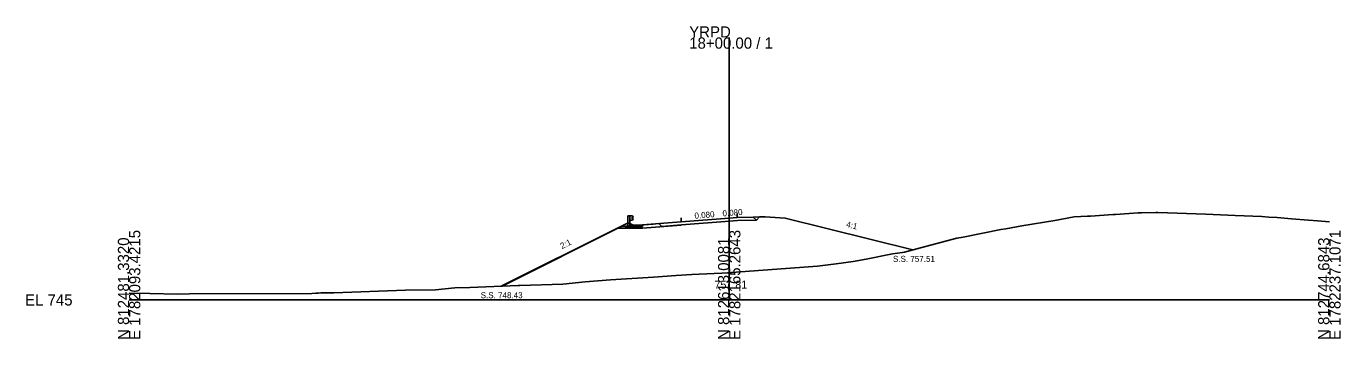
# Model space of a CAD drawing. Extents: x -26 to 1403, y -10 to 9544.
# Drawn here: x -25.7 to 302.8, y 7990.3 to 8068.4 of the extents above; entities that cross this region are included whole.
import ezdxf

# ---------------------------------------------------------------- set-up
doc = ezdxf.new("R2010")
doc.units = 0
for name, color, linetype in [('Exist Cross Section Cell', 7, 'Continuous'), ('Exist XS Center Line Elevation Label', 7, 'Continuous'), ('Exist XS Ground Line', 7, 'Continuous'), ('Prop XS Dump Level', 7, 'Continuous'), ('Prop XS Earthwork Shape', 7, 'Continuous'), ('Prop XS EOT Tick Mark', 7, 'Continuous'), ('Prop XS Finish Grade', 7, 'Continuous'), ('Prop XS Finish Grade CurbGutter', 7, 'Continuous'), ('Prop XS Finish Grade Earthwork', 7, 'Continuous'), ('Prop XS Finish Grade Paved Shoulder', 7, 'Continuous'), ('Prop XS Finish Grade Pavement', 7, 'Continuous'), ('Prop XS Guardrail', 7, 'Continuous'), ('Prop XS Pvmt Edge Slope', 7, 'Continuous'), ('Prop XS SE Text', 7, 'Continuous'), ('Prop XS Side Slope Text', 7, 'Continuous'), ('Prop XS SS Elevation Text', 7, 'Continuous'), ('Prop XS Subgrade CurbGutter', 7, 'Continuous'), ('Prop XS Subgrade Earthwork', 7, 'Continuous')]:
    doc.layers.add(name, color=color, linetype=linetype)

msp = doc.modelspace()

# ---------------------------------------------------------------- linework, layer by layer
at = {"layer": 'Exist Cross Section Cell'}
for p, q in [((150, 8000), (150, 8065.58)), ((0, 8000), (150, 8000)), ((150, 8000), (300, 8000))]:
    msp.add_line(p, q, dxfattribs=at)
at = {"layer": 'Exist XS Ground Line'}
for p, q in [((223.12, 8018.51), (231.37, 8019.86)), ((231.37, 8019.86), (236.24, 8020.8)), ((236.24, 8020.8), (239.53, 8020.93)), ((239.53, 8020.93), (240.32, 8020.96)), ((240.32, 8020.96), (245.93, 8021.33)), ((245.93, 8021.33), (246.56, 8021.37)), ((246.56, 8021.37), (249.98, 8021.6)), ((249.98, 8021.6), (252.25, 8021.76)), ((252.25, 8021.76), (253.01, 8021.77)), ((253.01, 8021.77), (256.62, 8021.85)), ((256.62, 8021.85), (257.15, 8021.86)), ((257.15, 8021.86), (269.12, 8021.47)), ((269.12, 8021.47), (276.47, 8021.13)), ((276.47, 8021.13), (283.13, 8020.82)), ((283.13, 8020.82), (284.86, 8020.72)), ((284.86, 8020.72), (286.99, 8020.6)), ((286.99, 8020.6), (290.53, 8020.3)), ((290.53, 8020.3), (294.79, 8019.94)), ((294.79, 8019.94), (297.02, 8019.77)), ((297.02, 8019.77), (300, 8019.55)), ((208.48, 8015.66), (217.86, 8017.6)), ((217.86, 8017.6), (219.11, 8017.8)), ((219.11, 8017.8), (223.12, 8018.51)), ((193.81, 8011.95), (199.08, 8013.38)), ((199.08, 8013.38), (206.85, 8015.46)), ((206.85, 8015.46), (208.48, 8015.66)), ((180.94, 8009.57), (184.2, 8010.15)), ((184.2, 8010.15), (190.82, 8011.53)), ((190.82, 8011.53), (193.32, 8011.89)), ((193.32, 8011.89), (193.81, 8011.95)), ((136.78, 8006.09), (140.62, 8006.35)), ((140.62, 8006.35), (150, 8006.81)), ((150, 8006.81), (150.56, 8006.84)), ((150.56, 8006.84), (172.08, 8008.47)), ((172.08, 8008.47), (176.75, 8008.98)), ((176.75, 8008.98), (180.94, 8009.57)), ((81.38, 8002.99), (85.17, 8003.13)), ((85.17, 8003.13), (97.24, 8003.59)), ((97.24, 8003.59), (97.68, 8003.59)), ((97.68, 8003.59), (108.44, 8003.97)), ((108.44, 8003.97), (114.01, 8004.51)), ((114.01, 8004.51), (120.31, 8005.02)), ((120.31, 8005.02), (131.1, 8005.71)), ((131.1, 8005.71), (136.78, 8006.09)), ((0, 8001.72), (5.18, 8001.63)), ((5.18, 8001.63), (12.13, 8001.45)), ((12.13, 8001.45), (15.1, 8001.54)), ((15.1, 8001.54), (45.71, 8001.64)), ((45.71, 8001.64), (46.7, 8001.68)), ((46.7, 8001.68), (47.36, 8001.69)), ((47.36, 8001.69), (47.94, 8001.73)), ((47.94, 8001.73), (51.2, 8001.8)), ((51.2, 8001.8), (69.13, 8002.4)), ((69.13, 8002.4), (76.61, 8002.55)), ((76.61, 8002.55), (81.38, 8002.99))]:
    msp.add_line(p, q, dxfattribs=at)
at = {"layer": 'Prop XS Dump Level'}
for p, q in [((138, 8019.51), (150, 8020.47)), ((150, 8020.47), (152, 8020.63))]:
    msp.add_line(p, q, dxfattribs=at)
at = {"layer": 'Prop XS Earthwork Shape'}
msp.add_lwpolyline([(193.81, 8011.95), (195.87, 8012.51), (164, 8020.47), (159, 8020.77), (157.58, 8020.75), (156.78, 8019.94), (152.04, 8019.84), (150.06, 8019.69), (138.06, 8018.73), (133.14, 8018.33), (132.4, 8019.07), (131, 8018.95), (123, 8018.31), (93.24, 8003.44), (97.24, 8003.59), (97.68, 8003.59), (108.44, 8003.97), (114.01, 8004.51), (120.31, 8005.02), (131.1, 8005.71), (136.78, 8006.09), (140.62, 8006.35), (150, 8006.81), (150.56, 8006.84), (172.08, 8008.47), (176.75, 8008.98), (180.94, 8009.57), (184.2, 8010.15), (190.82, 8011.53), (193.32, 8011.89)], close=True, dxfattribs=at)
at = {"layer": 'Prop XS EOT Tick Mark'}
for p, q in [((138, 8019.51), (138, 8020.51)), ((152, 8020.63), (152, 8021.63))]:
    msp.add_line(p, q, dxfattribs=at)
at = {"layer": 'Prop XS Finish Grade'}
for p, q in [((156, 8020.71), (157.58, 8020.75)), ((122.07, 8017.95), (124.73, 8019.28)), ((125.31, 8018.99), (124.73, 8019.28))]:
    msp.add_line(p, q, dxfattribs=at)
at = {"layer": 'Prop XS Finish Grade CurbGutter'}
for p, q in [((126, 8018.65), (125.31, 8018.99)), ((128.33, 8018.74), (126, 8018.65))]:
    msp.add_line(p, q, dxfattribs=at)
at = {"layer": 'Prop XS Finish Grade Earthwork'}
for p, q in [((157.58, 8020.75), (159, 8020.77)), ((159, 8020.77), (164, 8020.47)), ((164, 8020.47), (195.87, 8012.51)), ((122.07, 8017.95), (93.03, 8003.43))]:
    msp.add_line(p, q, dxfattribs=at)
at = {"layer": 'Prop XS Finish Grade Paved Shoulder'}
for p, q in [((138, 8019.51), (128.33, 8018.74)), ((152, 8020.63), (156, 8020.71))]:
    msp.add_line(p, q, dxfattribs=at)
at = {"layer": 'Prop XS Finish Grade Pavement'}
for p, q in [((138, 8019.51), (150, 8020.47)), ((150, 8020.47), (152, 8020.63))]:
    msp.add_line(p, q, dxfattribs=at)
at = {"layer": 'Prop XS Guardrail'}
for p, q in [((124.68, 8021.04), (125.18, 8021.04)), ((124.68, 8018.54), (124.68, 8021.04)), ((125.18, 8021.04), (125.68, 8021.04)), ((125.18, 8021.04), (125.18, 8018.54)), ((125.68, 8019.91), (125.18, 8019.91)), ((125.68, 8021.04), (125.97, 8020.84)), ((125.97, 8020.72), (125.68, 8020.52)), ((125.68, 8020.52), (125.68, 8020.43)), ((125.68, 8020.43), (125.97, 8020.23)), ((125.97, 8020.11), (125.68, 8019.91)), ((125.97, 8020.84), (126, 8020.78)), ((126, 8020.78), (125.97, 8020.72)), ((125.97, 8020.23), (126, 8020.17)), ((126, 8020.17), (125.97, 8020.11))]:
    msp.add_line(p, q, dxfattribs=at)
at = {"layer": 'Prop XS Pvmt Edge Slope'}
for p, q in [((156, 8020.71), (156.78, 8019.94)), ((124.31, 8018.32), (123.94, 8017.95)), ((125.31, 8018.32), (124.31, 8018.32))]:
    msp.add_line(p, q, dxfattribs=at)
at = {"layer": 'Prop XS Subgrade CurbGutter'}
for p, q in [((125.31, 8018.32), (125.31, 8018.99)), ((128.33, 8018.32), (125.31, 8018.32)), ((128.33, 8018.74), (128.33, 8018.32))]:
    msp.add_line(p, q, dxfattribs=at)
at = {"layer": 'Prop XS Subgrade Earthwork'}
for p, q in [((138.06, 8018.73), (150.06, 8019.69)), ((150.06, 8019.69), (152.04, 8019.84)), ((152.04, 8019.84), (156.78, 8019.94)), ((156.78, 8019.94), (157.58, 8020.75)), ((123.94, 8017.95), (122.07, 8017.95)), ((128.33, 8017.95), (123.94, 8017.95)), ((138, 8018.72), (128.33, 8017.95)), ((128.33, 8017.95), (128.33, 8017.95))]:
    msp.add_line(p, q, dxfattribs=at)

# ---------------------------------------------------------------- texts
at = {"layer": 'Exist Cross Section Cell'}
for s, p in [('YRPD', (140, 8065.58)), ('18+00.00 / 1', (140, 8062.78)), ('EL 745', (-26, 7998.6))]:
    msp.add_text(s, height=2.8, dxfattribs=at).set_placement(p)
for s, p in [('E 1782093.4215', (2.8, 7990)), ('E 1782165.2643', (152.8, 7990)), ('E 1782237.1071', (302.8, 7990)), ('N 812481.3320', (0, 7990)), ('N 812613.0081', (150, 7990)), ('N 812744.6843', (300, 7990))]:
    msp.add_text(s, height=2.8, rotation=90, dxfattribs=at).set_placement(p)
at = {"layer": 'Exist XS Center Line Elevation Label'}
msp.add_text('751.81', height=2, dxfattribs=at).set_placement((146.32, 8002.81))
at = {"layer": 'Prop XS Dump Level'}
for s, p in [('Case4', (164, 8020.43)), ('Case4', (126, 8018.51)), ('Case2', (128.33, 8018.7))]:
    msp.add_text(s, height=0.04, dxfattribs=at).set_placement(p)
at = {"layer": 'Prop XS SE Text'}
for p in [(141.38, 8020.29), (148.38, 8020.85)]:
    msp.add_text('0.080', height=1.5, rotation=4.5739, dxfattribs=at).set_placement(p)
at = {"layer": 'Prop XS Side Slope Text'}
for s, rotation, p in [('4:1', 345.9638, (179.12, 8018.24)), ('2:1', 26.5651, (108.21, 8012.69))]:
    msp.add_text(s, height=1.5, rotation=rotation, dxfattribs=at).set_placement(p)
at = {"layer": 'Prop XS SS Elevation Text'}
for s, p in [('S.S. 757.51', (190.93, 8009.51)), ('S.S. 748.43', (87.88, 8000.43))]:
    msp.add_text(s, height=1.5, dxfattribs=at).set_placement(p)

doc.saveas('drawing.dxf')
